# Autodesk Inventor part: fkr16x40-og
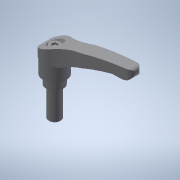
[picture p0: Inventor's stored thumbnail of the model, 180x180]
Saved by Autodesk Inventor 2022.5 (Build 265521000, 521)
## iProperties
Created: 2017-09
Part Number: fkr16x40-og
Material: 一般
Document SubType Name: Modeling
Designer: imaocorp
Density: 1 g/cm^3
Appearance: 既定
Author: imaocorp
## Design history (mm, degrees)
node "fkr16x40-og.x_t1"
node "fkr16x40-og"
node "Base1"
